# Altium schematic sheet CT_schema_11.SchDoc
size 385 x 385 mm
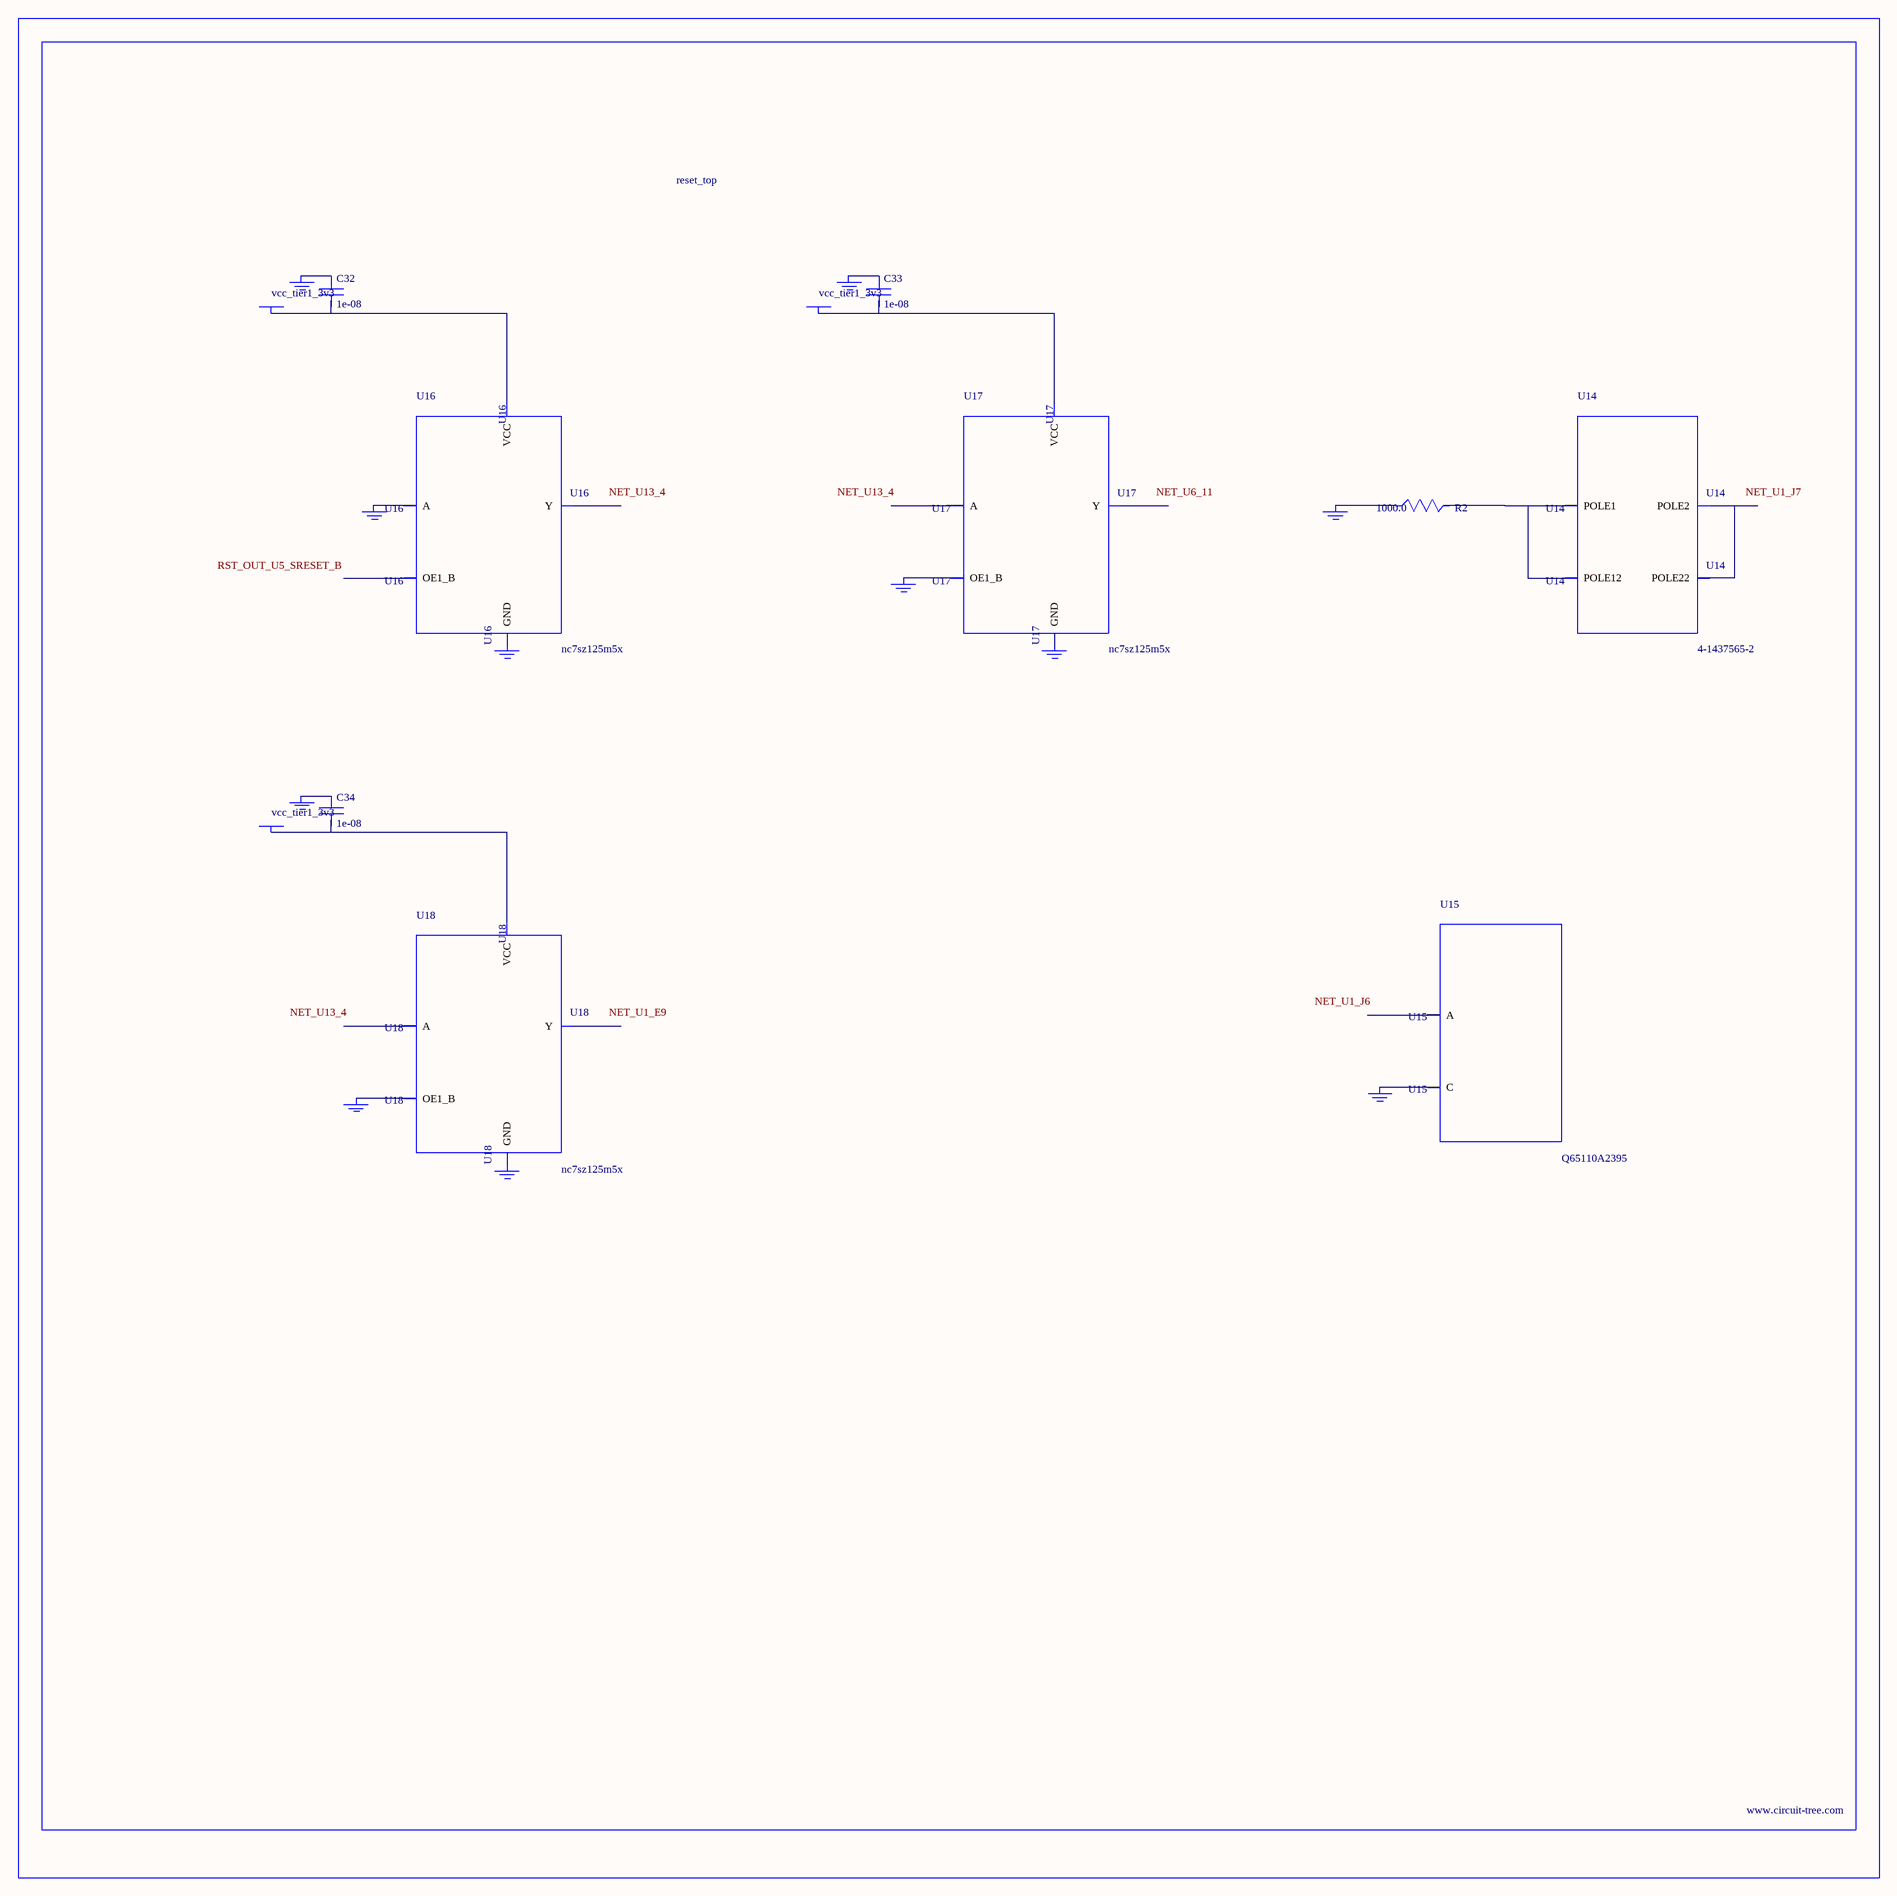
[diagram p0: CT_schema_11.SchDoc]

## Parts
BORDER10  (no value)
C32  1e-08  [C0402]
C33  1e-08  [C0402]
C34  1e-08  [C0402]
GND_INSTANCE_10_0  (no value)
GND_INSTANCE_10_1  (no value)
GND_INSTANCE_10_2  (no value)
GND_INSTANCE_10_3  (no value)
GND_INSTANCE_10_4  (no value)
GND_INSTANCE_10_5  (no value)
GND_INSTANCE_10_6  (no value)
GND_INSTANCE_10_7  (no value)
GND_INSTANCE_10_8  (no value)
GND_INSTANCE_10_9  (no value)
GND_INSTANCE_10_10  (no value)
POWER_INSTANCE_10_0  vcc_tier1_3v3
POWER_INSTANCE_10_1  vcc_tier1_3v3
POWER_INSTANCE_10_2  vcc_tier1_3v3
R2  1000.0  [R0603]
U14  4-1437565-2  [SW_4-1437565-2]
U15  Q65110A2395  [LGM67K-G1J2-24-Z]
U16  nc7sz125m5x  [NC7SZ125M5X]
U17  nc7sz125m5x  [NC7SZ125M5X]
U18  nc7sz125m5x  [NC7SZ125M5X]

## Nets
NetC32_1: C32.1 GND_INSTANCE_10_2.0(GND)
NetC32_2: C32.2 POWER_INSTANCE_10_0.0(PWR) U16.5(VCC)
NetC33_1: C33.1 GND_INSTANCE_10_5.0(GND)
NetC33_2: C33.2 POWER_INSTANCE_10_1.0(PWR) U17.5(VCC)
NetC34_1: C34.1 GND_INSTANCE_10_8.0(GND)
NetC34_2: C34.2 POWER_INSTANCE_10_2.0(PWR) U18.5(VCC)
NetGND_INSTANCE_10_0_0: GND_INSTANCE_10_0.0(GND) R2.1
NetGND_INSTANCE_10_1_0: GND_INSTANCE_10_1.0(GND) U15.C
NetGND_INSTANCE_10_3_0: GND_INSTANCE_10_3.0(GND) U16.2(A)
NetGND_INSTANCE_10_4_0: GND_INSTANCE_10_4.0(GND) U16.3(GND)
NetGND_INSTANCE_10_6_0: GND_INSTANCE_10_6.0(GND) U17.1(OE1_B)
NetGND_INSTANCE_10_7_0: GND_INSTANCE_10_7.0(GND) U17.3(GND)
NetGND_INSTANCE_10_9_0: GND_INSTANCE_10_9.0(GND) U18.1(OE1_B)
NetGND_INSTANCE_10_10_0: GND_INSTANCE_10_10.0(GND) U18.3(GND)
NetR2_2: R2.2 U14.1(POLE1) U14.2(POLE12)
NetU14_3: U14.3(POLE2) U14.4(POLE22)

Not connected (* = marked no-connect by the designer): U15 A; U16 1(OE1_B) 4(Y); U17 2(A) 4(Y); U18 2(A) 4(Y)

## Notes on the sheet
- Labels drawn without touching a wire or pin: NET_U1_E9, NET_U1_J6, NET_U1_J7, NET_U6_11, NET_U13_4, RST_OUT_U5_SRESET_B

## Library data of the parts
BORDER10 = BORDER_PAGE10
C32-C34 = C0402C103K3RAC
GND_INSTANCE_10_0-GND_INSTANCE_10_10 = GND
POWER_INSTANCE_10_0-POWER_INSTANCE_10_2 = PWR
R2 = RC0603JR-071KL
